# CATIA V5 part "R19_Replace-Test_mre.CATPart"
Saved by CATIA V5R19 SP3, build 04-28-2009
Part number: Part1
Bounding box of the stored display mesh (mm): x -20 to 100, y 0 to 50, z -14.142 to 14.142
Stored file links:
  P:\fb\CCC\AKU\040_CATIA-Daten\R19_Replace-Test_mre.CATPart

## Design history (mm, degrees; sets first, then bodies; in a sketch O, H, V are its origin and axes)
Body1
  Set1
    Sphere1: Center Point2, Radius 20, Angle1 -45, Angle3 0, Angle4 180
Body2 (main body)
  Body3
    Set2
      Point1: (100, 50, 0)
      Line1: type PtPt, FirstPoint Point2, SecondPoint Point1
    Set3
      Point2: (0, 0, 0)
      Point3: (100, 0, 0)
  Add1: tool Body3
